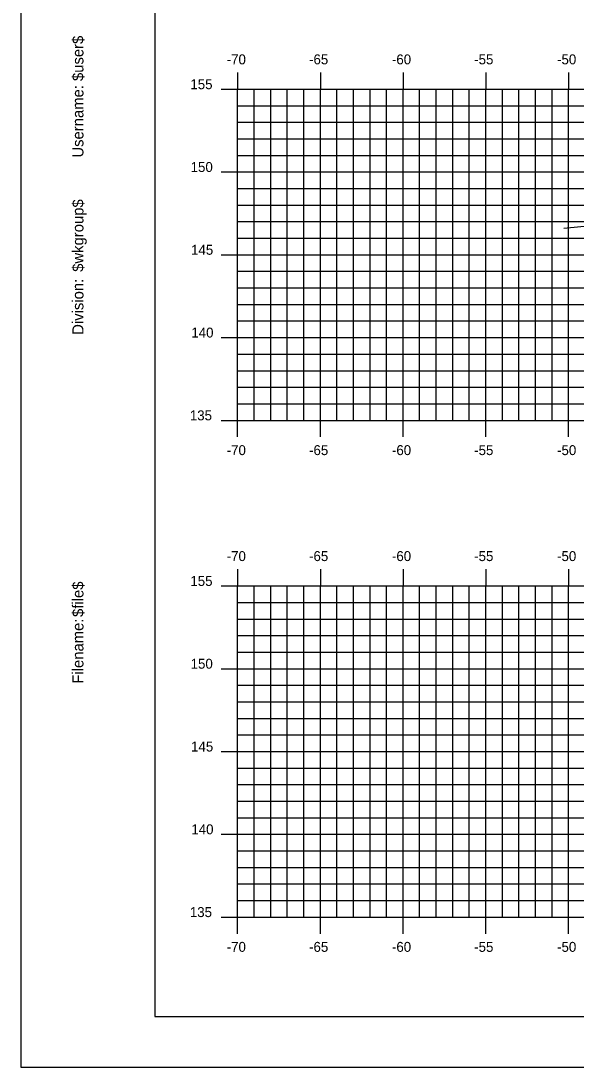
# Model space of a CAD drawing. Extents: x 1144751 to 1144921, y 608981 to 609091.
# Drawn here: x 1144750.5 to 1144784.1, y 608981.3 to 609044.5 of the extents above; entities that cross this region are included whole.
import ezdxf

# ---------------------------------------------------------------- set-up
doc = ezdxf.new("R2010")
doc.units = 0
for name, color, linetype in [('BORDER', 7, 'Continuous'), ('H_V ANNOTATION', 7, 'Continuous'), ('MAJOR', 7, 'Continuous'), ('MINOR', 7, 'Continuous'), ('PLOT BOUNDARY', 7, 'Continuous'), ('S_Roadway_Centerline', 7, 'Continuous')]:
    doc.layers.add(name, color=color, linetype=linetype)

msp = doc.modelspace()

# ---------------------------------------------------------------- linework, layer by layer
at = {"layer": 'BORDER'}
msp.add_lwpolyline([(1144758.619, 608984.335), (1144918.619, 608984.335), (1144918.619, 609089.335), (1144758.619, 609089.335)], close=True, dxfattribs=at)
at = {"layer": 'MAJOR'}
for p, q in [((1144763.619, 609041.337), (1144763.619, 609040.335)), ((1144768.619, 609041.337), (1144768.619, 609040.335)), ((1144773.619, 609041.337), (1144773.619, 609040.335)), ((1144778.619, 609041.337), (1144778.619, 609040.335)), ((1144783.619, 609041.337), (1144783.619, 609040.335)), ((1144762.617, 609040.335), (1144763.619, 609040.335)), ((1144763.619, 609040.335), (1144903.619, 609040.335)), ((1144763.619, 609020.335), (1144763.619, 609040.335)), ((1144763.619, 609020.335), (1144763.619, 609040.335)), ((1144763.619, 609040.335), (1144903.619, 609040.335)), ((1144768.619, 609020.335), (1144768.619, 609040.335)), ((1144773.619, 609020.335), (1144773.619, 609040.335)), ((1144778.619, 609020.335), (1144778.619, 609040.335)), ((1144783.619, 609020.335), (1144783.619, 609040.335)), ((1144762.617, 609035.335), (1144763.619, 609035.335)), ((1144763.619, 609035.335), (1144903.619, 609035.335)), ((1144762.617, 609030.335), (1144763.619, 609030.335)), ((1144763.619, 609030.335), (1144903.619, 609030.335)), ((1144762.617, 609025.335), (1144763.619, 609025.335)), ((1144763.619, 609025.335), (1144903.619, 609025.335)), ((1144762.617, 609020.335), (1144763.619, 609020.335)), ((1144763.619, 609020.335), (1144903.619, 609020.335)), ((1144763.619, 609020.335), (1144903.619, 609020.335)), ((1144763.619, 609019.333), (1144763.619, 609020.335)), ((1144768.619, 609019.333), (1144768.619, 609020.335)), ((1144773.619, 609019.333), (1144773.619, 609020.335)), ((1144778.619, 609019.333), (1144778.619, 609020.335)), ((1144783.619, 609019.333), (1144783.619, 609020.335)), ((1144763.619, 609011.337), (1144763.619, 609010.335)), ((1144768.619, 609011.337), (1144768.619, 609010.335)), ((1144773.619, 609011.337), (1144773.619, 609010.335)), ((1144778.619, 609011.337), (1144778.619, 609010.335)), ((1144783.619, 609011.337), (1144783.619, 609010.335)), ((1144762.617, 609010.335), (1144763.619, 609010.335)), ((1144763.619, 609010.335), (1144903.619, 609010.335)), ((1144763.619, 608990.335), (1144763.619, 609010.335)), ((1144763.619, 608990.335), (1144763.619, 609010.335)), ((1144763.619, 609010.335), (1144903.619, 609010.335)), ((1144768.619, 608990.335), (1144768.619, 609010.335)), ((1144773.619, 608990.335), (1144773.619, 609010.335)), ((1144778.619, 608990.335), (1144778.619, 609010.335)), ((1144783.619, 608990.335), (1144783.619, 609010.335)), ((1144762.617, 609005.335), (1144763.619, 609005.335)), ((1144763.619, 609005.335), (1144903.619, 609005.335)), ((1144762.617, 609000.335), (1144763.619, 609000.335)), ((1144763.619, 609000.335), (1144903.619, 609000.335)), ((1144762.617, 608995.335), (1144763.619, 608995.335)), ((1144763.619, 608995.335), (1144903.619, 608995.335)), ((1144762.617, 608990.335), (1144763.619, 608990.335)), ((1144763.619, 608990.335), (1144903.619, 608990.335)), ((1144763.619, 608990.335), (1144903.619, 608990.335)), ((1144763.619, 608989.333), (1144763.619, 608990.335)), ((1144768.619, 608989.333), (1144768.619, 608990.335)), ((1144773.619, 608989.333), (1144773.619, 608990.335)), ((1144778.619, 608989.333), (1144778.619, 608990.335)), ((1144783.619, 608989.333), (1144783.619, 608990.335))]:
    msp.add_line(p, q, dxfattribs=at)
at = {"layer": 'MINOR'}
for p, q in [((1144764.619, 609020.335), (1144764.619, 609040.335)), ((1144765.619, 609020.335), (1144765.619, 609040.335)), ((1144766.619, 609020.335), (1144766.619, 609040.335)), ((1144767.619, 609020.335), (1144767.619, 609040.335)), ((1144769.619, 609020.335), (1144769.619, 609040.335)), ((1144770.619, 609020.335), (1144770.619, 609040.335)), ((1144771.619, 609020.335), (1144771.619, 609040.335)), ((1144772.619, 609020.335), (1144772.619, 609040.335)), ((1144774.619, 609020.335), (1144774.619, 609040.335)), ((1144775.619, 609020.335), (1144775.619, 609040.335)), ((1144776.619, 609020.335), (1144776.619, 609040.335)), ((1144777.619, 609020.335), (1144777.619, 609040.335)), ((1144779.619, 609020.335), (1144779.619, 609040.335)), ((1144780.619, 609020.335), (1144780.619, 609040.335)), ((1144781.619, 609020.335), (1144781.619, 609040.335)), ((1144782.619, 609020.335), (1144782.619, 609040.335)), ((1144763.619, 609039.335), (1144903.619, 609039.335)), ((1144763.619, 609039.335), (1144764.621, 609039.335)), ((1144763.619, 609038.335), (1144903.619, 609038.335)), ((1144763.619, 609038.335), (1144764.621, 609038.335)), ((1144763.619, 609037.335), (1144903.619, 609037.335)), ((1144763.619, 609037.335), (1144764.621, 609037.335)), ((1144763.619, 609036.335), (1144903.619, 609036.335)), ((1144763.619, 609036.335), (1144764.621, 609036.335)), ((1144763.619, 609034.335), (1144903.619, 609034.335)), ((1144763.619, 609034.335), (1144764.621, 609034.335)), ((1144763.619, 609033.335), (1144903.619, 609033.335)), ((1144763.619, 609033.335), (1144764.621, 609033.335)), ((1144763.619, 609032.335), (1144903.619, 609032.335)), ((1144763.619, 609032.335), (1144764.621, 609032.335)), ((1144763.619, 609031.335), (1144903.619, 609031.335)), ((1144763.619, 609031.335), (1144764.621, 609031.335)), ((1144763.619, 609029.335), (1144903.619, 609029.335)), ((1144763.619, 609029.335), (1144764.621, 609029.335)), ((1144763.619, 609028.335), (1144903.619, 609028.335)), ((1144763.619, 609028.335), (1144764.621, 609028.335)), ((1144763.619, 609027.335), (1144903.619, 609027.335)), ((1144763.619, 609027.335), (1144764.621, 609027.335)), ((1144763.619, 609026.335), (1144903.619, 609026.335)), ((1144763.619, 609026.335), (1144764.621, 609026.335)), ((1144763.619, 609024.335), (1144903.619, 609024.335)), ((1144763.619, 609024.335), (1144764.621, 609024.335)), ((1144763.619, 609023.335), (1144903.619, 609023.335)), ((1144763.619, 609023.335), (1144764.621, 609023.335)), ((1144763.619, 609022.335), (1144903.619, 609022.335)), ((1144763.619, 609022.335), (1144764.621, 609022.335)), ((1144763.619, 609021.335), (1144903.619, 609021.335)), ((1144763.619, 609021.335), (1144764.621, 609021.335)), ((1144764.619, 608990.335), (1144764.619, 609010.335)), ((1144765.619, 608990.335), (1144765.619, 609010.335)), ((1144766.619, 608990.335), (1144766.619, 609010.335)), ((1144767.619, 608990.335), (1144767.619, 609010.335)), ((1144769.619, 608990.335), (1144769.619, 609010.335)), ((1144770.619, 608990.335), (1144770.619, 609010.335)), ((1144771.619, 608990.335), (1144771.619, 609010.335)), ((1144772.619, 608990.335), (1144772.619, 609010.335)), ((1144774.619, 608990.335), (1144774.619, 609010.335)), ((1144775.619, 608990.335), (1144775.619, 609010.335)), ((1144776.619, 608990.335), (1144776.619, 609010.335)), ((1144777.619, 608990.335), (1144777.619, 609010.335)), ((1144779.619, 608990.335), (1144779.619, 609010.335)), ((1144780.619, 608990.335), (1144780.619, 609010.335)), ((1144781.619, 608990.335), (1144781.619, 609010.335)), ((1144782.619, 608990.335), (1144782.619, 609010.335)), ((1144763.619, 609009.335), (1144903.619, 609009.335)), ((1144763.619, 609009.335), (1144764.621, 609009.335)), ((1144763.619, 609008.335), (1144903.619, 609008.335)), ((1144763.619, 609008.335), (1144764.621, 609008.335)), ((1144763.619, 609007.335), (1144903.619, 609007.335)), ((1144763.619, 609007.335), (1144764.621, 609007.335)), ((1144763.619, 609006.335), (1144903.619, 609006.335)), ((1144763.619, 609006.335), (1144764.621, 609006.335)), ((1144763.619, 609004.335), (1144903.619, 609004.335)), ((1144763.619, 609004.335), (1144764.621, 609004.335)), ((1144763.619, 609003.335), (1144903.619, 609003.335)), ((1144763.619, 609003.335), (1144764.621, 609003.335)), ((1144763.619, 609002.335), (1144903.619, 609002.335)), ((1144763.619, 609002.335), (1144764.621, 609002.335)), ((1144763.619, 609001.335), (1144903.619, 609001.335)), ((1144763.619, 609001.335), (1144764.621, 609001.335)), ((1144763.619, 608999.335), (1144903.619, 608999.335)), ((1144763.619, 608999.335), (1144764.621, 608999.335)), ((1144763.619, 608998.335), (1144903.619, 608998.335)), ((1144763.619, 608998.335), (1144764.621, 608998.335)), ((1144763.619, 608997.335), (1144903.619, 608997.335)), ((1144763.619, 608997.335), (1144764.621, 608997.335)), ((1144763.619, 608996.335), (1144903.619, 608996.335)), ((1144763.619, 608996.335), (1144764.621, 608996.335)), ((1144763.619, 608994.335), (1144903.619, 608994.335)), ((1144763.619, 608994.335), (1144764.621, 608994.335)), ((1144763.619, 608993.335), (1144903.619, 608993.335)), ((1144763.619, 608993.335), (1144764.621, 608993.335)), ((1144763.619, 608992.335), (1144903.619, 608992.335)), ((1144763.619, 608992.335), (1144764.621, 608992.335)), ((1144763.619, 608991.335), (1144903.619, 608991.335)), ((1144763.619, 608991.335), (1144764.621, 608991.335))]:
    msp.add_line(p, q, dxfattribs=at)
at = {"layer": 'PLOT BOUNDARY'}
msp.add_lwpolyline([(1144750.526, 608981.276), (1144920.526, 608981.276), (1144920.526, 609091.276), (1144750.526, 609091.276)], close=True, dxfattribs=at)
at = {"layer": 'S_Roadway_Centerline'}
msp.add_lwpolyline([(1144783.338, 609031.937), (1144785.588, 609032.156), (1144803.411, 609031.709), (1144806.171, 609031.584), (1144812.1, 609030.451), (1144812.366, 609030.413), (1144812.487, 609030.445), (1144817.107, 609031.177), (1144819.29, 609031.161), (1144819.463, 609031.18), (1144820.262, 609031.19), (1144830.751, 609031.377), (1144840.894, 609030.911), (1144841.691, 609030.885), (1144841.859, 609030.863), (1144846.068, 609030.451), (1144846.347, 609030.396), (1144849.307, 609029.907), (1144849.614, 609029.914), (1144853.774, 609030.361), (1144875.416, 609029.679), (1144877.702, 609029.675)], dxfattribs=at)

# ---------------------------------------------------------------- texts
at = {"layer": 'BORDER'}
for s, p in [('$user$', (1144754.304, 609040.827)), ('Username:', (1144754.304, 609036.203)), ('$wkgroup$', (1144754.304, 609029.305)), ('Division:', (1144754.304, 609025.501)), ('$file$', (1144754.304, 609008.461)), ('Filename:', (1144754.304, 609004.433))]:
    msp.add_text(s, height=0.6696, rotation=90, dxfattribs=at).set_placement(p)
at = {"layer": 'H_V ANNOTATION'}
for s, p in [('-70', (1144762.96, 609041.835)), ('-65', (1144767.937, 609041.835)), ('-60', (1144772.945, 609041.835)), ('-55', (1144777.915, 609041.835)), ('-50', (1144782.923, 609041.835)), ('155', (1144760.765, 609040.335)), ('150', (1144760.781, 609035.335)), ('145', (1144760.808, 609030.335)), ('140', (1144760.824, 609025.335)), ('135', (1144760.733, 609020.335)), ('-70', (1144762.96, 609018.235)), ('-65', (1144767.937, 609018.235)), ('-60', (1144772.945, 609018.235)), ('-55', (1144777.915, 609018.235)), ('-50', (1144782.923, 609018.235)), ('-70', (1144762.96, 609011.835)), ('-65', (1144767.937, 609011.835)), ('-60', (1144772.945, 609011.835)), ('-55', (1144777.915, 609011.835)), ('-50', (1144782.923, 609011.835)), ('155', (1144760.765, 609010.335)), ('150', (1144760.781, 609005.335)), ('145', (1144760.808, 609000.335)), ('140', (1144760.824, 608995.335)), ('135', (1144760.733, 608990.335)), ('-70', (1144762.96, 608988.235)), ('-65', (1144767.937, 608988.235)), ('-60', (1144772.945, 608988.235)), ('-55', (1144777.915, 608988.235)), ('-50', (1144782.923, 608988.235))]:
    msp.add_text(s, height=0.6, dxfattribs=at).set_placement(p)
at = {"layer": 'MAJOR'}
for p in [(1144763.614, 609020.335), (1144763.614, 608990.335)]:
    msp.add_text('-', height=0.006, dxfattribs=at).set_placement(p)

doc.saveas('drawing.dxf')
